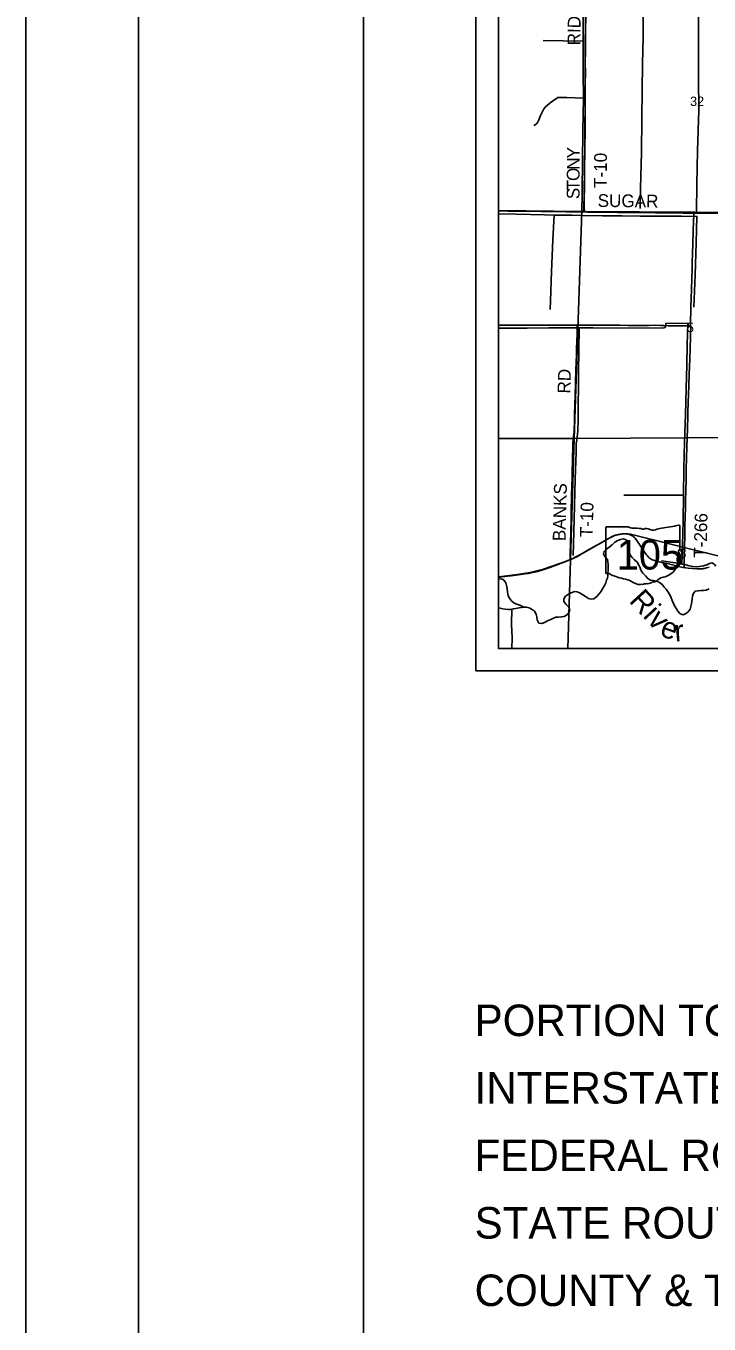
# Model space of a CAD drawing. Extents: x 0 to 34, y 0 to 22.
# Drawn here: x 0 to 3.04, y 11.1 to 16.87 of the extents above; entities that cross this region are included whole.
import ezdxf

# ---------------------------------------------------------------- set-up
doc = ezdxf.new("R2010")
doc.units = 0
for name, color, linetype in [('GM_X_City_Street', 7, 'Continuous'), ('GM_X_County_Road', 7, 'Continuous'), ('GM_X_County_Road_Text', 7, 'Continuous'), ('GM_X_Major_River', 7, 'Continuous'), ('GM_X_Major_River_Text', 7, 'Continuous'), ('GM_X_Minor_River', 7, 'Continuous'), ('GM_X_Rail_Line', 7, 'Continuous'), ('GM_X_Section', 7, 'Continuous'), ('GM_X_Section_Text', 7, 'Continuous'), ('GM_X_State_Location', 7, 'Continuous'), ('GM_X_State_Route', 7, 'Continuous'), ('GM_X_State_Shield', 7, 'Continuous'), ('GM_X_Township_Road', 7, 'Continuous'), ('GM_X_Township_Road_Text', 7, 'Continuous'), ('GM_X_US_Route', 7, 'Continuous'), ('SH_Border', 7, 'Continuous'), ('SH_Cut_Line', 7, 'Continuous'), ('SH_Data', 7, 'Continuous'), ('SH_Text', 7, 'Continuous')]:
    doc.layers.add(name, color=color, linetype=linetype)

msp = doc.modelspace()

# ---------------------------------------------------------------- linework, layer by layer
at = {"layer": 'GM_X_City_Street'}
for points in [[(2.1, 17.0529), (2.1, 16.0468), (2.4708, 16.042), (2.4803, 16.0422), (2.4865, 16.4094), (2.4879, 17.0483)], [(2.1, 16.0468), (2.1, 15.0334), (2.4374, 15.0335), (2.4708, 16.042)], [(2.1, 15.0334), (2.1, 14.1), (2.4083, 14.1), (2.4374, 15.0335)], [(2.4083, 14.1), (3.4093, 14.1), (3.4378, 15.0391), (2.4374, 15.0335)]]:
    msp.add_lwpolyline(points, close=True, dxfattribs=at)
at = {"layer": 'GM_X_County_Road'}
for points in [[(2.1, 16.0446), (2.1421, 16.0442), (2.2291, 16.0436), (2.2913, 16.0428), (2.3503, 16.0419), (2.4001, 16.0413), (2.4498, 16.0405), (2.4824, 16.0401)], [(2.4824, 16.0401), (2.4964, 16.0399), (2.5834, 16.0389), (2.6301, 16.0384), (2.7171, 16.0375), (2.7979, 16.0367), (2.8787, 16.0358), (2.9222, 16.0354), (2.9693, 16.0348)], [(2.9693, 16.0348), (2.9813, 16.0347), (3.0341, 16.0344), (3.0838, 16.0342), (3.1833, 16.0334), (3.2517, 16.0331), (3.3107, 16.0325), (3.3542, 16.0321), (3.404, 16.0314), (3.4537, 16.0307), (3.4718, 16.0303)]]:
    msp.add_lwpolyline(points, dxfattribs=at)
at = {"layer": 'GM_X_Major_River'}
for points in [[(3.0375, 14.3655), (3.024, 14.3589), (3.0115, 14.358), (2.9997, 14.3571), (2.9876, 14.3566), (2.9742, 14.3538), (2.9657, 14.3425), (2.9636, 14.3323), (2.9611, 14.3206), (2.9605, 14.3103), (2.9584, 14.2978), (2.9563, 14.2865), (2.9523, 14.2751), (2.9437, 14.2631), (2.9321, 14.2535), (2.9195, 14.2499), (2.9067, 14.2547), (2.8978, 14.2655), (2.8916, 14.2763), (2.8835, 14.2894), (2.8784, 14.2997), (2.8729, 14.3135), (2.8682, 14.3254), (2.8631, 14.3357), (2.8546, 14.3507), (2.8457, 14.3627), (2.8376, 14.3723), (2.8276, 14.3847), (2.8156, 14.3933), (2.8028, 14.3989), (2.7888, 14.4014), (2.7767, 14.4039), (2.7639, 14.4106), (2.7547, 14.4233), (2.7427, 14.435), (2.7335, 14.4481), (2.7299, 14.4576), (2.7248, 14.4707), (2.7175, 14.4837), (2.7055, 14.4942), (2.694, 14.5062), (2.6828, 14.5197), (2.6774, 14.5324), (2.6768, 14.5445), (2.6782, 14.5574), (2.6773, 14.5704), (2.6681, 14.5823), (2.6552, 14.5864), (2.6431, 14.5847), (2.6304, 14.58), (2.6178, 14.5723), (2.6054, 14.5604), (2.5927, 14.5496), (2.5812, 14.5418), (2.57, 14.5314), (2.5674, 14.5189), (2.5748, 14.507), (2.5845, 14.495), (2.5869, 14.4855), (2.5882, 14.4729), (2.5887, 14.4592), (2.5877, 14.4459), (2.5871, 14.4345), (2.5866, 14.4246), (2.5844, 14.4129), (2.5812, 14.4031), (2.5772, 14.3921), (2.5713, 14.379), (2.565, 14.368), (2.5572, 14.3549), (2.5478, 14.3429), (2.537, 14.331), (2.5243, 14.3209), (2.5129, 14.3193), (2.5, 14.3218), (2.4869, 14.3304), (2.4753, 14.3375), (2.4636, 14.3449), (2.4509, 14.3516), (2.4387, 14.3526), (2.4242, 14.3468), (2.4116, 14.341), (2.3989, 14.3317), (2.3903, 14.3205), (2.3905, 14.3083), (2.4012, 14.2959), (2.4117, 14.2851), (2.4175, 14.2728), (2.4147, 14.2626), (2.4076, 14.251), (2.3928, 14.2425), (2.3812, 14.2401), (2.3679, 14.2395), (2.3558, 14.2386), (2.3428, 14.2336), (2.3328, 14.2288), (2.3186, 14.2219), (2.3056, 14.2157)], [(2.3056, 14.2157), (2.293, 14.2106), (2.2805, 14.2127), (2.2728, 14.2269), (2.2716, 14.2406), (2.2684, 14.2525), (2.2606, 14.2652), (2.2471, 14.2745), (2.237, 14.2804), (2.2245, 14.283), (2.2128, 14.2836), (2.2033, 14.2822), (2.1925, 14.2808), (2.1781, 14.2781), (2.1659, 14.2753), (2.153, 14.2733), (2.1431, 14.2735), (2.1303, 14.2749), (2.1193, 14.2762), (2.1083, 14.2783), (2.1, 14.2805)]]:
    msp.add_lwpolyline(points, dxfattribs=at)
at = {"layer": 'GM_X_Minor_River'}
for points in [[(3.0025, 18.2), (3.0007, 18.1194), (2.9984, 18.0416), (2.9959, 17.7375), (2.994, 17.5136), (2.9923, 17.3464), (2.9916, 17.2438), (2.9912, 17.1096), (2.9894, 17.0203), (2.99, 16.8918), (2.99, 16.7606), (2.9898, 16.6333), (2.9904, 16.4933), (2.9852, 16.3125), (2.9825, 16.1643), (2.9813, 16.0408)], [(2.476, 18.1459), (2.4771, 18.0771), (2.4781, 18.0432), (2.4793, 17.9146), (2.4784, 17.8158), (2.4785, 17.6976), (2.4786, 17.5432), (2.4789, 17.4216), (2.4779, 17.2775), (2.4774, 17.1296), (2.4761, 17.0289), (2.4773, 16.9103), (2.4771, 16.7989), (2.4777, 16.6578), (2.479, 16.5464), (2.4756, 16.3998), (2.474, 16.2629), (2.4723, 16.1379), (2.4714, 16.025)], [(2.7445, 17.0292), (2.7434, 16.819), (2.7411, 16.6982), (2.7389, 16.5808), (2.738, 16.4546), (2.736, 16.306), (2.7325, 16.1438), (2.7308, 16.0548)], [(2.4771, 16.7989), (2.2988, 16.8017)], [(2.479, 16.5464), (2.4047, 16.5482), (2.3648, 16.5482), (2.3455, 16.5362), (2.3308, 16.5256), (2.3082, 16.5061), (2.3003, 16.496), (2.2866, 16.4683), (2.2797, 16.4502), (2.2736, 16.4383), (2.2689, 16.4323), (2.2634, 16.4271), (2.258, 16.4243)], [(2.1, 16.0312), (2.1785, 16.03), (2.3056, 16.0279), (2.3481, 16.0259), (2.4278, 16.0255), (2.4714, 16.025), (2.5625, 16.0236), (2.6494, 16.023), (2.7302, 16.0218), (2.8216, 16.0207), (2.9135, 16.0219), (2.9826, 16.0202), (2.9789, 15.9029), (2.9748, 15.7593), (2.9696, 15.6169)], [(2.3481, 16.0259), (2.3427, 15.9169), (2.3364, 15.7749), (2.3311, 15.6454), (2.33, 15.6059)], [(2.9158, 14.4747), (2.9186, 14.5594), (2.9212, 14.6658), (2.9234, 14.7806), (2.9245, 14.8999), (2.9275, 15.0188), (2.9317, 15.1385), (2.9346, 15.2559), (2.9375, 15.3585), (2.9398, 15.4497), (2.9428, 15.5442), (2.8449, 15.5451), (2.8426, 15.5308), (2.8414, 15.527), (2.836, 15.5249), (2.6488, 15.5238), (2.5213, 15.5244), (2.4598, 15.525), (2.3239, 15.5244), (2.2279, 15.5241), (2.1037, 15.5242), (2.1, 15.5242)], [(2.4598, 15.525), (2.4556, 15.3251), (2.454, 15.1206), (2.4532, 15.0648), (2.4521, 15.0549), (2.4497, 15.0356), (2.4455, 15.0072), (2.4456, 14.973), (2.4414, 14.8518), (2.4384, 14.7333), (2.4355, 14.6185), (2.4325, 14.5133)], [(2.9234, 14.7806), (2.7939, 14.7805), (2.658, 14.781)], [(3.0668, 14.4649), (3.0615, 14.4732), (3.0571, 14.4767), (3.0492, 14.48), (3.0392, 14.4772), (3.0269, 14.4719), (3.0113, 14.4678), (2.9937, 14.4641), (2.9792, 14.463), (2.9641, 14.4638), (2.9494, 14.4673), (2.9332, 14.4715), (2.9158, 14.4747), (2.886, 14.4801), (2.8255, 14.4898)], [(2.2128, 14.2836), (2.195, 14.2916), (2.1774, 14.2989), (2.1684, 14.3022), (2.1588, 14.3116), (2.1489, 14.3233), (2.1439, 14.3334), (2.1405, 14.3498), (2.1395, 14.3662), (2.134, 14.3872), (2.1301, 14.3965), (2.1212, 14.4059), (2.113, 14.4088), (2.1027, 14.4079), (2.1, 14.4073)], [(2.1604, 14.2745), (2.1589, 14.2078), (2.1613, 14.1473), (2.1595, 14.1)]]:
    msp.add_lwpolyline(points, dxfattribs=at)
at = {"layer": 'GM_X_Rail_Line'}
msp.add_lwpolyline([(2.1, 14.4174), (2.1014, 14.4177), (2.1855, 14.4285), (2.241, 14.437), (2.3004, 14.4524), (2.3729, 14.4779), (2.4215, 14.4956), (2.4817, 14.5265), (2.5511, 14.5666), (2.6082, 14.5983), (2.6321, 14.6067), (2.6645, 14.6114), (2.6869, 14.6075), (3.0811, 14.5095)], dxfattribs=at)
at = {"layer": 'GM_X_Section'}
msp.add_lwpolyline([(3.4773, 16.1435), (3.4754, 16.0365), (3.4686, 16.0366), (2.4803, 16.0422), (2.4865, 16.4094), (2.4879, 17.0483), (3.4934, 17.0475), (3.4907, 16.8935)], dxfattribs=at)
msp.add_lwpolyline([(2.4708, 16.042), (2.4803, 16.0422), (3.4686, 16.0366), (3.4378, 15.0391), (2.4374, 15.0335)], close=True, dxfattribs=at)
at = {"layer": 'GM_X_State_Route'}
for points in [[(2.5901, 14.5884), (2.598, 14.5928), (2.6026, 14.5952), (2.6069, 14.5973), (2.6122, 14.5996), (2.6164, 14.6012), (2.6209, 14.6028), (2.6264, 14.6045), (2.6319, 14.6058), (2.6382, 14.607), (2.6431, 14.6077), (2.6473, 14.6082), (2.6515, 14.6086), (2.656, 14.6091), (2.6611, 14.6093), (2.6646, 14.6093), (2.6677, 14.6092), (2.6709, 14.6089), (2.6752, 14.6084), (2.6792, 14.6075), (2.683, 14.6064), (2.6864, 14.6052), (2.6892, 14.6039), (2.6921, 14.6024), (2.6964, 14.5998), (2.699, 14.598), (2.7014, 14.5961), (2.7038, 14.5939), (2.7059, 14.5918), (2.7077, 14.5898), (2.7113, 14.5854), (2.7156, 14.5792)], [(2.1, 14.4159), (2.1078, 14.4174), (2.1176, 14.419), (2.1238, 14.4198), (2.1294, 14.4203), (2.1566, 14.4231), (2.1776, 14.4255), (2.1893, 14.427), (2.2176, 14.4309), (2.2335, 14.4335), (2.2457, 14.4358), (2.2621, 14.4392), (2.2736, 14.442), (2.298, 14.4492), (2.3116, 14.4536), (2.3198, 14.4565), (2.3284, 14.4599), (2.3477, 14.467), (2.3681, 14.4745), (2.3745, 14.4769), (2.385, 14.4808), (2.4006, 14.4869), (2.4093, 14.4902), (2.4211, 14.4948), (2.4226, 14.4954), (2.4289, 14.4982), (2.4385, 14.5025), (2.4484, 14.5075), (2.483, 14.5272), (2.498, 14.536), (2.5115, 14.5436), (2.5381, 14.5586), (2.5527, 14.5668), (2.5775, 14.5811), (2.5866, 14.5865), (2.5901, 14.5884)], [(2.7156, 14.5792), (2.7269, 14.5621), (2.7417, 14.5391), (2.7492, 14.5284), (2.7574, 14.5175), (2.7624, 14.5112), (2.7665, 14.5066), (2.7705, 14.5029), (2.7743, 14.4998), (2.7789, 14.4968), (2.7838, 14.4942), (2.7889, 14.492), (2.7941, 14.4902), (2.8014, 14.488), (2.8085, 14.4863), (2.828, 14.4819), (2.8497, 14.4771), (2.9083, 14.463), (2.9205, 14.4604), (2.9255, 14.4596), (2.9327, 14.4584), (2.9437, 14.4569), (2.9625, 14.4551), (2.9818, 14.4536), (2.9889, 14.4533), (2.9963, 14.4531), (3.0007, 14.4533), (3.0048, 14.4536), (3.0086, 14.4541), (3.0118, 14.4545), (3.0166, 14.4553), (3.0211, 14.4564), (3.0259, 14.4578), (3.0311, 14.4596), (3.0367, 14.4619)]]:
    msp.add_lwpolyline(points, dxfattribs=at)
at = {"layer": 'GM_X_State_Shield'}
for p, q in [((2.5772, 14.6367), (2.5772, 14.4366)), ((2.677, 14.6402), (2.5805, 14.6402)), ((2.9068, 14.5404), (2.9068, 14.6451)), ((2.9068, 14.5405), (2.9068, 14.5404))]:
    msp.add_line(p, q, dxfattribs=at)
for centre, major_axis, start_param, end_param in [((2.581, 14.6372), (0.00382, 0), 1.712693, 3.28349), ((2.7, 14.6634), (0.037, 0), 4.042523, 4.731795), ((2.7122, 14.5278), (0.133, 0), 1.404758, 1.657858), ((2.7424, 14.6382), (0.0107, 0), 3.836095, 5.185415), ((2.7581, 14.6151), (0.0222, 0), 0.950623, 2.079405), ((2.7868, 14.6468), (0.0267, 0), 4.081561, 5.145723), ((2.834, 14.579), (0.0703, 0), 1.699011, 2.107814), ((2.7894, 14.913), (0.3495, 0), 4.814394, 5.042369), ((2.9031, 14.6456), (0.00367, 0), 6.141152, 7.989035), ((2.809, 14.4833), (0.0874, 0), 5.101752, 6.440018), ((2.9199, 14.4966), (0.0248, 0), 2.387724, 3.262537), ((2.9059, 14.5328), (0.00568, 0), 1.883978, 3.671073), ((2.8698, 14.5195), (0.0341, 0), 5.934695, 6.695948), ((2.9029, 14.54), (0.00393, 0), 5.05454, 6.418171), ((2.581, 14.4362), (0.00385, 0), 3.00124, 4.508301), ((2.5816, 14.4566), (0.0294, 0), 4.665946, 4.897461), ((2.5876, 14.4251), (0.0106, 0), 0.519207, 1.627899), ((2.7214, 14.6049), (0.2524, 0), 4.195997, 4.488961), ((2.6462, 14.3467), (0.079, 0), 0.823519, 1.323587), ((2.7316, 14.4241), (0.0501, 0), 4.026481, 4.996735), ((2.7606, 14.3549), (0.0412, 0), 1.495662, 1.94098), ((2.7642, 14.4091), (0.0267, 0), 4.691044, 5.507374), ((2.7884, 14.3897), (0.00752, 0), 1.147584, 2.315152), ((2.7852, 14.4172), (0.0282, 0), 4.937069, 5.64225), ((2.8458, 14.3804), (0.0479, 0), 1.647645, 2.488434)]:
    msp.add_ellipse(centre, major_axis=major_axis, ratio=0.8, start_param=start_param, end_param=end_param, dxfattribs=at)
at = {"layer": 'GM_X_Township_Road'}
for points in [[(2.4824, 16.0401), (2.4822, 16.0478), (2.4819, 16.0571), (2.482, 16.0944), (2.4824, 16.1504), (2.4829, 16.2095), (2.4833, 16.2561), (2.484, 16.3245), (2.4846, 16.3959), (2.4847, 16.427), (2.4858, 16.5016), (2.4863, 16.5327), (2.4865, 16.5576), (2.4865, 16.6166), (2.4866, 16.6539), (2.4861, 16.7068), (2.4858, 16.7379), (2.4865, 16.8032), (2.4874, 16.8529), (2.4881, 16.9026), (2.4887, 16.9617), (2.4891, 17.0021), (2.4899, 17.0522)], [(2.9546, 15.5358), (2.9544, 15.5442), (2.9544, 15.566), (2.9549, 15.5909), (2.9557, 15.6188), (2.9571, 15.6561), (2.9583, 15.6965), (2.9596, 15.7432), (2.961, 15.7867), (2.9621, 15.8178), (2.9633, 15.8519), (2.9664, 15.9514), (2.9677, 16.0043), (2.9684, 16.0198), (2.9689, 16.0291), (2.9693, 16.0348)], [(2.1, 15.5371), (2.118, 15.5371), (2.174, 15.5371), (2.2175, 15.537), (2.2641, 15.5368), (2.3014, 15.5367), (2.3294, 15.5365), (2.3854, 15.5368), (2.4351, 15.5371), (2.4508, 15.5371)], [(2.4211, 14.4948), (2.4199, 14.5003), (2.4191, 14.504), (2.4189, 14.5093), (2.4193, 14.522), (2.4202, 14.5687), (2.4214, 14.6153), (2.4229, 14.6775), (2.4236, 14.7178), (2.4251, 14.7677), (2.4257, 14.7894), (2.4264, 14.8174), (2.4274, 14.8671), (2.4295, 14.9511), (2.4304, 14.9882), (2.4309, 15.0039), (2.4313, 15.0164), (2.4318, 15.0259), (2.4326, 15.0315), (2.4342, 15.0411), (2.4357, 15.0534), (2.4365, 15.0627), (2.4372, 15.0751), (2.4381, 15.1062), (2.439, 15.1404), (2.4401, 15.1839), (2.4414, 15.2243), (2.4447, 15.3363), (2.4468, 15.4047), (2.4477, 15.4326), (2.4497, 15.4979), (2.4506, 15.5197), (2.4507, 15.5321), (2.4508, 15.5371)], [(2.4508, 15.5371), (2.4848, 15.5371), (2.519, 15.5368), (2.5594, 15.5368), (2.578, 15.5366), (2.5966, 15.5365), (2.6402, 15.5363), (2.6775, 15.5359), (2.7054, 15.5357), (2.7396, 15.5355), (2.7676, 15.5358), (2.7987, 15.5362), (2.8204, 15.536), (2.836, 15.5355), (2.8546, 15.5344), (2.867, 15.534), (2.8888, 15.5338), (2.923, 15.5334), (2.9354, 15.5335), (2.9416, 15.5338), (2.9476, 15.5345), (2.9521, 15.5354), (2.9546, 15.5358)], [(2.9255, 14.4596), (2.9255, 14.4653), (2.9256, 14.4733), (2.9266, 14.5247), (2.9282, 14.5931), (2.9293, 14.6428), (2.9305, 14.6832), (2.9315, 14.7268), (2.9322, 14.7579), (2.9333, 14.8014), (2.9346, 14.8541), (2.9353, 14.8834), (2.9355, 14.904), (2.9362, 14.9413), (2.938, 15.0003), (2.9387, 15.0314), (2.9404, 15.0812), (2.942, 15.1309), (2.9426, 15.1495), (2.9441, 15.193), (2.9452, 15.2303), (2.9464, 15.2676), (2.9486, 15.3236), (2.9495, 15.3484), (2.9526, 15.4323), (2.9543, 15.4852), (2.9548, 15.5038), (2.9549, 15.5225), (2.9546, 15.5358)]]:
    msp.add_lwpolyline(points, dxfattribs=at)
at = {"layer": 'GM_X_US_Route'}
msp.add_lwpolyline([(2.1, 19.0771), (2.1, 14.1), (3.4084, 14.1)], dxfattribs=at)
at = {"layer": 'SH_Border'}
for points in [[(0.5, 21.5), (1.5, 21.5), (1.5, 0.5), (0.5, 0.5)], [(1.5, 21.5), (33.5, 21.5), (33.5, 0.5), (1.5, 0.5)]]:
    msp.add_lwpolyline(points, close=True, dxfattribs=at)
at = {"layer": 'SH_Cut_Line'}
msp.add_lwpolyline([(0, 0), (34, 0), (34, 22), (0, 22)], close=True, dxfattribs=at)
msp.add_lwpolyline([(2.1, 20.9), (2.1, 14.1), (7.4244, 14.1)], dxfattribs=at)
at = {"layer": 'SH_Data'}
for p, q in [((2, 21), (2, 14)), ((2.1, 20.9), (2.1, 14.1)), ((2.1, 14.1), (8.9, 14.1)), ((2.1, 14.1), (2.1, 14.1)), ((2, 14), (9, 14))]:
    msp.add_line(p, q, dxfattribs=at)

# ---------------------------------------------------------------- texts
at = {"layer": 'GM_X_County_Road_Text'}
msp.add_text('SUGAR', height=0.05682, rotation=359.39328, dxfattribs=at).set_placement((2.5411, 16.0625))
at = {"layer": 'GM_X_Major_River_Text'}
for s, height, rotation, p in [('Riv', 0.09476, 312.42762, (2.6774, 14.3091)), ('e', 0.0948, 340.42875, (2.8134, 14.1578)), ('r', 0.0948, 4.43071, (2.8856, 14.1302))]:
    msp.add_text(s, height=height, rotation=rotation, dxfattribs=at).set_placement(p)
at = {"layer": 'GM_X_Section_Text'}
for s, height, p in [('32', 0.04186, (2.9523, 16.511)), ('5', 0.0419, (2.9381, 15.5057)), ('8', 0.0419, (2.9048, 14.5027))]:
    msp.add_text(s, height=height, rotation=0.00001, dxfattribs=at).set_placement(p)
at = {"layer": 'GM_X_State_Location'}
msp.add_text('105', height=0.000189, rotation=0.00001, dxfattribs=at).set_placement((2.6714, 14.5096))
for s in ['s', 'r']:
    msp.add_text(s, height=0.000189, dxfattribs=at).set_placement((2.7383, 14.5234))
at = {"layer": 'GM_X_State_Shield'}
msp.add_text('105', height=0.13184, dxfattribs=at).set_placement((2.6263, 14.4507))
at = {"layer": 'GM_X_Township_Road_Text'}
for s, height, rotation, p in [('RIDGE', 0.05682, 89.32552, (2.4641, 16.7804)), ('N', 0.0568, 89.79155, (2.4612, 16.2277)), ('Y', 0.0568, 89.14756, (2.4614, 16.2775)), ('T-10', 0.05682, 89.6467, (2.5817, 16.1467)), ('O', 0.0568, 89.78872, (2.461, 16.1777)), ('T', 0.0568, 89.78999, (2.4609, 16.1352)), ('S', 0.0568, 89.79093, (2.4608, 16.0969)), ('RD', 0.05682, 88.51931, (2.4199, 15.2324)), ('BANKS', 0.05682, 88.57796, (2.3983, 14.5764)), ('T-10', 0.05682, 88.58498, (2.5192, 14.5935)), ('T-266', 0.05682, 88.60994, (3.025, 14.5024))]:
    msp.add_text(s, height=height, rotation=rotation, dxfattribs=at).set_placement(p)
at = {"layer": 'SH_Text'}
for s, p in [('PORTION TO BE IMPROVED', (1.9944, 12.3767)), ('INTERSTATE HIGHWAY', (1.9944, 12.0767)), ('FEDERAL ROUTES', (1.9944, 11.7767)), ('STATE ROUTES', (1.9944, 11.4767)), ('COUNTY & TOWNSHIP ROADS', (1.9944, 11.1767))]:
    msp.add_text(s, height=0.14, dxfattribs=at).set_placement(p)

doc.saveas('drawing.dxf')
